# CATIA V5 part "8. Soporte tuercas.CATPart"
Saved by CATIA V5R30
Part number: 8. Soporte tuercas
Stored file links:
  C:\Users\valen\Desktop\Estandar CubeSat - Programa AVES-20220531T050024Z-001\Estandar CubeSat - Programa AVES\3D - MODELS\CATIA\8. Soporte tuercas.CATPart

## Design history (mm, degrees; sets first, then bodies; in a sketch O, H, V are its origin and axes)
Body1 "Sólido1" (main body)
  Solid1: solid without history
